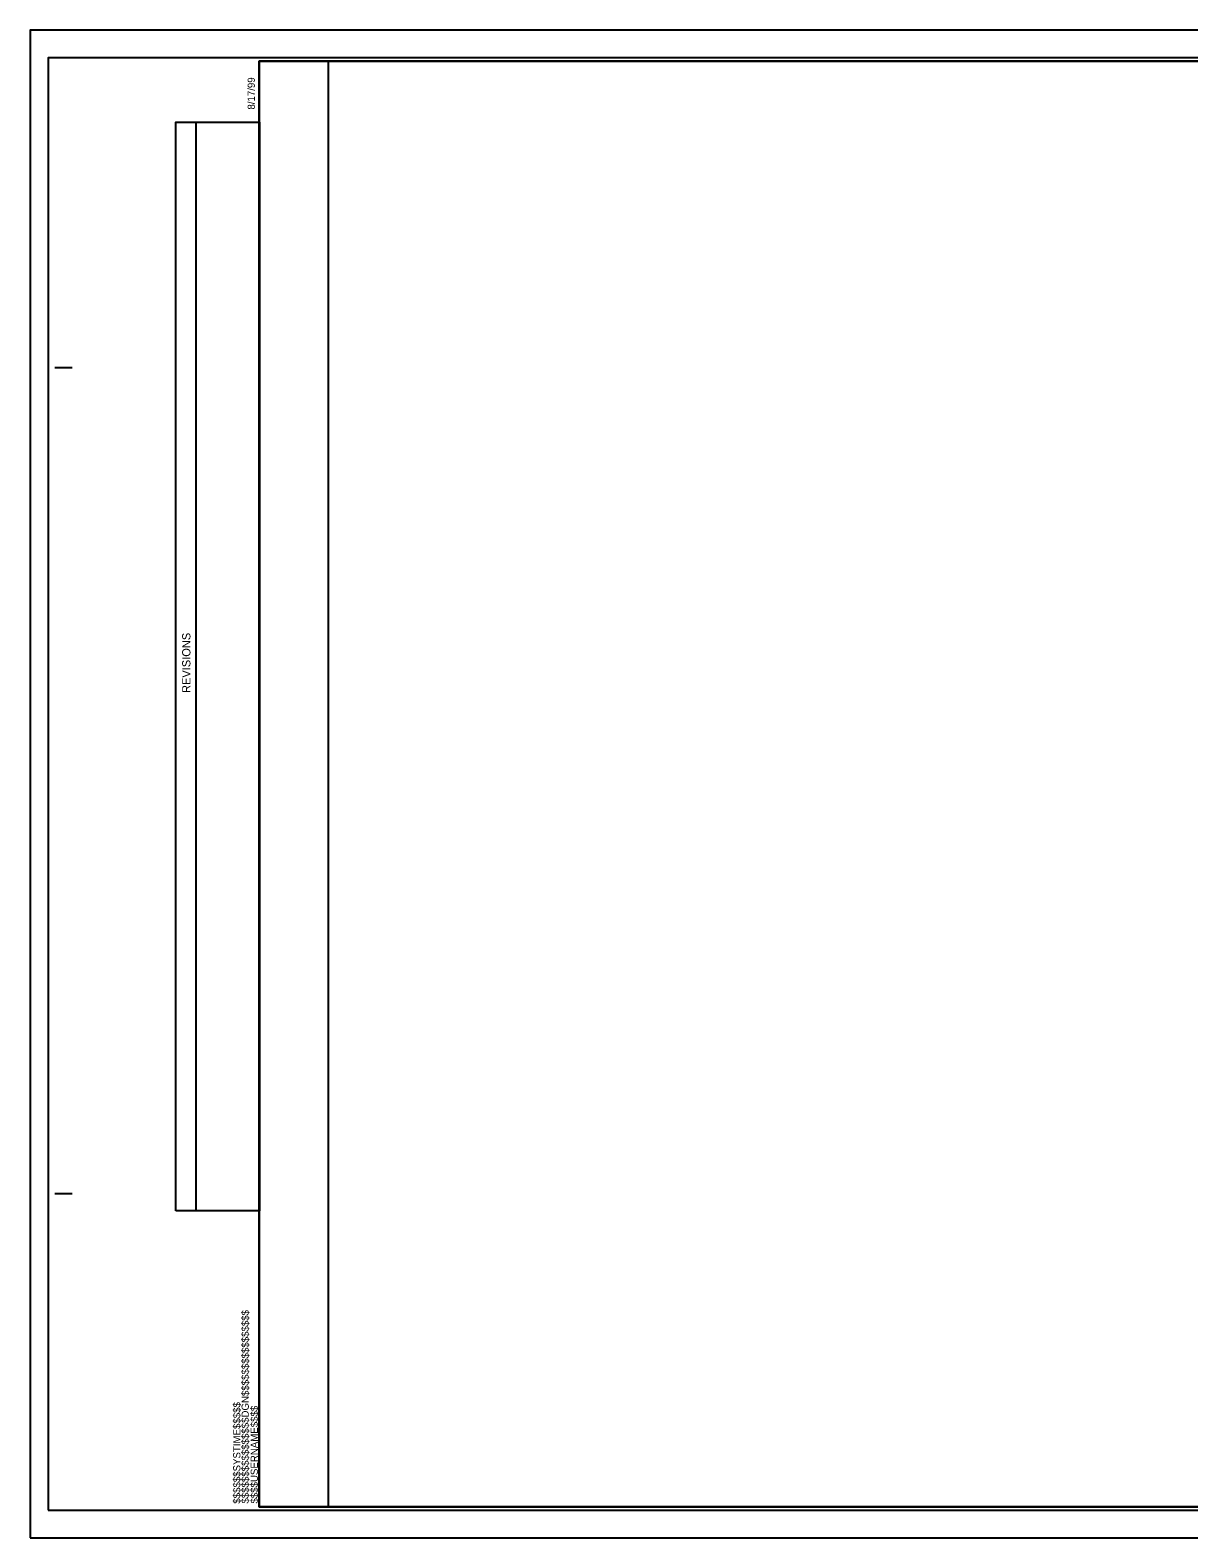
# Model space of a CAD drawing. Extents: x 2044275 to 2045958, y 759228 to 760388.
# Drawn here: x 2044275 to 2045117, y 759228 to 760323 of the extents above; entities that cross this region are included whole.
import ezdxf

# ---------------------------------------------------------------- set-up
doc = ezdxf.new("R2010")
doc.units = 0
for name, color, linetype in [('Sheet Block Revision CELL', 7, 'Continuous'), ('Sheet Clip Boundary CELL', 7, 'Continuous'), ('Sheet Cutting Line CELL', 7, 'Continuous'), ('Sheet Plan And Profile CELL', 7, 'Continuous'), ('Sheet Plan CELL', 7, 'Continuous'), ('Sheet Plot Border Inside CELL', 7, 'Continuous'), ('Sheet Plot Border Outside CELL', 7, 'Continuous')]:
    doc.layers.add(name, color=color, linetype=linetype)

msp = doc.modelspace()

# ---------------------------------------------------------------- linework, layer by layer
at = {"layer": 'Sheet Block Revision CELL'}
msp.add_line((2044395.4, 759465.8), (2044395.4, 760256.4), dxfattribs=at)
msp.add_lwpolyline([(2044380.8, 759465.8), (2044380.8, 760256.4), (2044441.4, 760256.4), (2044441.4, 759465.8)], close=True, dxfattribs=at)
at = {"layer": 'Sheet Clip Boundary CELL'}
msp.add_lwpolyline([(2044491.3, 759250.8), (2045891.4, 759250.8), (2045891.4, 760089.3), (2045702.1, 760089.3), (2045702.1, 760300.8), (2044491.3, 760300.8)], close=True, dxfattribs=at)
at = {"layer": 'Sheet Cutting Line CELL'}
for p, q in [((2045958.4, 760323.3), (2044274.9, 760323.3)), ((2044274.9, 760323.3), (2044274.9, 759228.3)), ((2044274.9, 759228.3), (2045958.4, 759228.3))]:
    msp.add_line(p, q, dxfattribs=at)
at = {"layer": 'Sheet Plan CELL'}
for p, q in [((2044441.3, 760300.8), (2044441.3, 760300.8)), ((2044292.8, 760078.3), (2044305.4, 760078.3)), ((2044292.9, 759478.3), (2044305.4, 759478.3)), ((2044441.3, 759250.8), (2044441.3, 759250.8))]:
    msp.add_line(p, q, dxfattribs=at)
for points in [[(2045941.4, 760300.8), (2044441.3, 760300.8), (2044441.3, 759250.8), (2045941.4, 759250.8)], [(2044441.3, 759250.8), (2044441.3, 760300.8), (2045741.3, 760300.8), (2045741.3, 760150.7), (2045941.4, 760150.7), (2045941.4, 759250.8)]]:
    msp.add_lwpolyline(points, close=True, dxfattribs=at)
at = {"layer": 'Sheet Plot Border Inside CELL'}
msp.add_lwpolyline([(2044287.9, 759248.3), (2045953.8, 759248.3), (2045953.9, 760303.3), (2044287.9, 760303.3)], close=True, dxfattribs=at)
at = {"layer": 'Sheet Plot Border Outside CELL'}
msp.add_lwpolyline([(2044274.9, 759228.3), (2045958.4, 759228.3), (2045958.4, 760323.3), (2044274.9, 760323.3)], close=True, dxfattribs=at)

# ---------------------------------------------------------------- texts
at = {"layer": 'Sheet Block Revision CELL'}
msp.add_text('REVISIONS', height=6, rotation=90, dxfattribs=at).set_placement((2044391.3, 759841.9))
at = {"layer": 'Sheet Plan And Profile CELL'}
msp.add_text('8/17/99', height=5.25, rotation=90, dxfattribs=at).set_placement((2044438.1, 760265.6))
at = {"layer": 'Sheet Plan CELL'}
for s, p in [('$$$$$$$$$$$$$$$$DGN$$$$$$$$$$$$$$$$', (2044433.7, 759253.2)), ('$$$$$$SYSTIME$$$$$', (2044427.6, 759253.1)), ('$$$$USERNAME$$$$', (2044440.3, 759253.2))]:
    msp.add_text(s, height=5.25, rotation=90, dxfattribs=at).set_placement(p)

doc.saveas('drawing.dxf')
